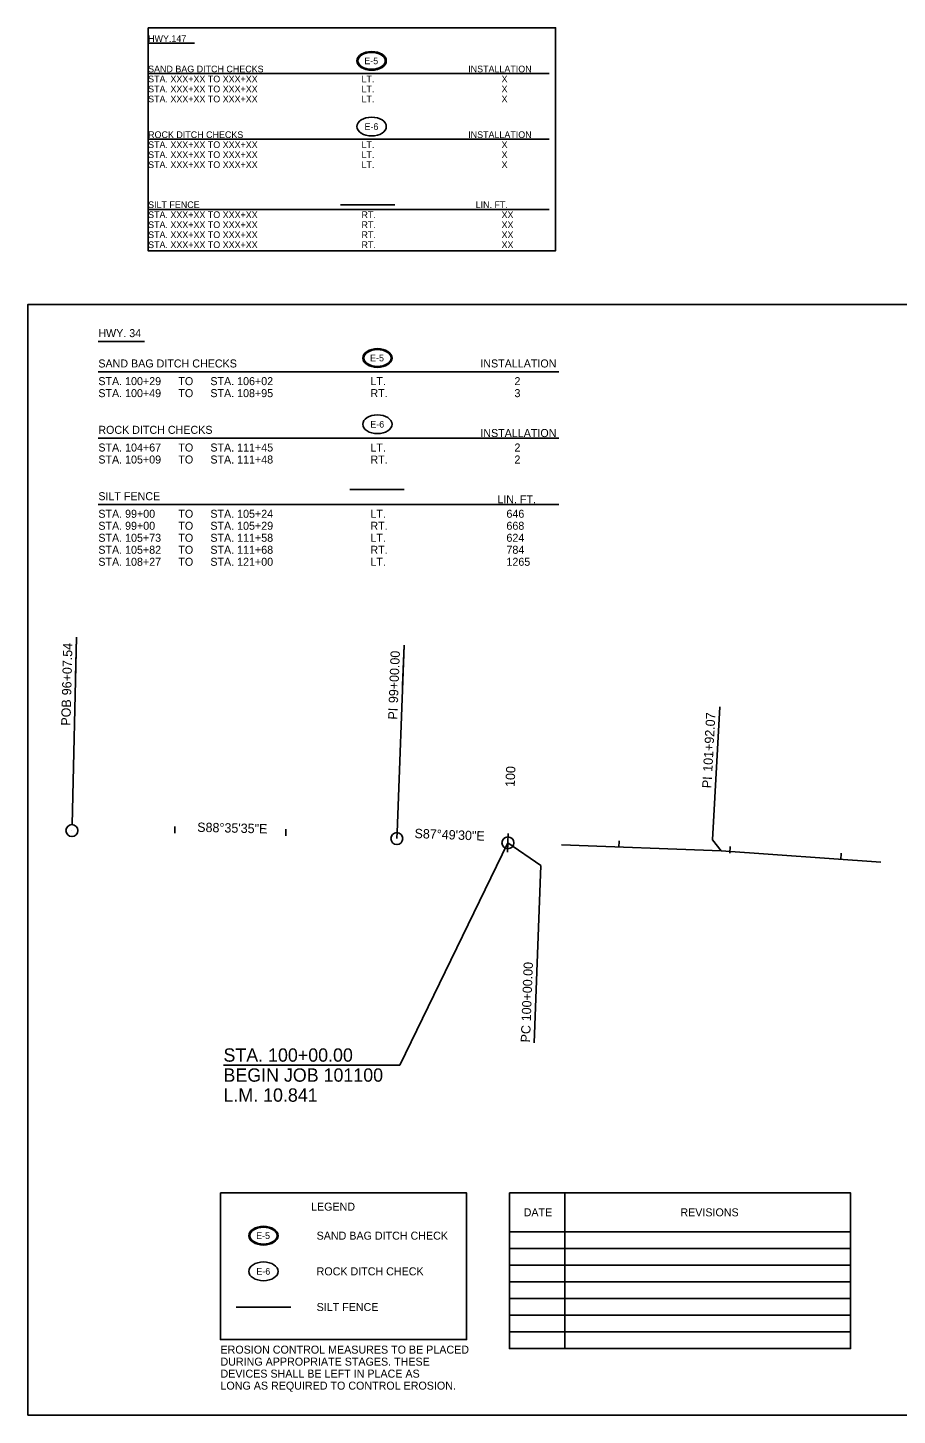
# Model space of a CAD drawing. Extents: x 1806834 to 1810084, y 678065 to 679314.
# Drawn here: x 1806834 to 1807616, y 678065 to 679314 of the extents above; entities that cross this region are included whole.
import ezdxf

# ---------------------------------------------------------------- set-up
doc = ezdxf.new("R2010")
doc.units = 0
for name, color, linetype in [('_CG DITCH CHECK', 7, 'Continuous'), ('_PROJECT LIMITS', 7, 'Continuous'), ('Default', 7, 'Continuous'), ('DSN_DRFT_Guideline-No-Plot', 7, 'Continuous'), ('DSN_RDWY_Alignment Annotation', 7, 'Continuous'), ('Erosion Legend', 7, 'Continuous'), ('R_Border Notes', 7, 'Continuous')]:
    doc.layers.add(name, color=color, linetype=linetype)

# ---------------------------------------------------------------- blocks, each defined once
blk = doc.blocks.new('E-6')
at = {"layer": 'Default'}
blk.add_ellipse((0, 0), major_axis=(1.32, 0), ratio=0.638788, dxfattribs=at)
blk.add_text('E-6', height=0.6, dxfattribs=at).set_placement((-0.64, -0.3))
blk = doc.blocks.new('E-5')
at = {"layer": 'Default'}
for major_axis, ratio in [((1.32, 0), 0.638788), ((-1.23, 0), 0.613481)]:
    blk.add_ellipse((0, 0), major_axis=major_axis, ratio=ratio, dxfattribs=at)
blk.add_text('E-5', height=0.6, dxfattribs=at).set_placement((-0.66, -0.3))

msp = doc.modelspace()

# ---------------------------------------------------------------- linework, layer by layer
at = {"layer": '_CG DITCH CHECK'}
for centre, major_axis, ratio in [((1807148.5, 679016.5), (13.2, 0), 0.638788), ((1807148.5, 679016.5), (-12.3, 0), 0.613481), ((1807046, 678227), (13.2, 0), 0.638788), ((1807046, 678227), (-12.3, 0), 0.613481)]:
    msp.add_ellipse(centre, major_axis=major_axis, ratio=ratio, dxfattribs=at)
at = {"layer": '_PROJECT LIMITS'}
for p, q in [((1807168.8, 678380.5), (1807265.9, 678580.4)), ((1807010, 678380.5), (1807168.8, 678380.5))]:
    msp.add_line(p, q, dxfattribs=at)
at = {"layer": 'Default'}
for p, q in [((1806897.3, 679031.4), (1806939, 679031.4)), ((1806897.3, 679004.1), (1807311.7, 679004.1)), ((1806897.3, 678944.4), (1807311.7, 678944.4)), ((1806897.3, 678884.7), (1807311.7, 678884.7)), ((1807317.2, 678265.5), (1807317.2, 678125.5)), ((1807267.2, 678230.5), (1807574.2, 678230.5)), ((1807267.2, 678215.5), (1807574.2, 678215.5)), ((1807267.2, 678200.5), (1807574.2, 678200.5)), ((1807267.2, 678185.5), (1807574.2, 678185.5)), ((1807267.2, 678170.5), (1807574.2, 678170.5)), ((1807267.2, 678155.5), (1807574.2, 678155.5)), ((1807267.2, 678140.5), (1807574.2, 678140.5))]:
    msp.add_line(p, q, dxfattribs=at)
for points in [[(1806942.2, 679313.6), (1807308.8, 679313.6), (1807308.8, 679113), (1806942.2, 679113)], [(1807007.3, 678265.5), (1807228.8, 678265.5), (1807228.8, 678133.5), (1807007.3, 678133.5)], [(1807267.2, 678265.5), (1807574.2, 678265.5), (1807574.2, 678125.5), (1807267.2, 678125.5)]]:
    msp.add_lwpolyline(points, close=True, dxfattribs=at)
at = {"layer": 'DSN_DRFT_Guideline-No-Plot'}
msp.add_lwpolyline([(1806833.9, 678065.5), (1808483.9, 678065.5), (1808483.9, 679064.5), (1806833.9, 679064.5)], close=True, dxfattribs=at)
at = {"layer": 'DSN_RDWY_Alignment Annotation'}
for p, q in [((1806873.8, 678596.8), (1806877.9, 678765.4)), ((1806877.9, 678765.4), (1806877, 678729.4)), ((1807166.2, 678589.6), (1807172.6, 678758.1)), ((1807172.6, 678758.1), (1807171.2, 678722.1)), ((1807450.1, 678583), (1807456.6, 678702.8)), ((1807456.6, 678702.8), (1807456.6, 678702.8)), ((1806873.6, 678591.4), (1806873.6, 678591.4)), ((1806966.2, 678595.2), (1806966.1, 678589.2)), ((1807066.2, 678592.7), (1807066, 678586.7)), ((1807166.2, 678590.2), (1807166, 678584.2)), ((1807266.2, 678588.8), (1807265.6, 678572.1)), ((1807166, 678584.2), (1807166, 678584.2)), ((1807265.9, 678580.4), (1807265.9, 678580.4)), ((1807295.4, 678559.9), (1807265.9, 678580.4)), ((1807457.9, 678573.2), (1807314, 678578.6)), ((1807366.1, 678582.2), (1807365.8, 678576.2)), ((1807450.1, 678583), (1807457.9, 678573.2)), ((1807466, 678577.1), (1807465.7, 678571.1)), ((1807457.9, 678573.2), (1807601.5, 678562.9)), ((1807565.9, 678571.1), (1807565.5, 678565.1)), ((1807295.4, 678559.9), (1807289.4, 678400.6)), ((1807289.4, 678400.6), (1807289.4, 678400.6))]:
    msp.add_line(p, q, dxfattribs=at)
for centre in [(1806873.6, 678591.4), (1807166, 678584.2), (1807265.9, 678580.4)]:
    msp.add_circle(centre, 5.34, dxfattribs=at)
at = {"layer": 'Erosion Legend'}
for p, q in [((1806942.1, 679299.7), (1806983.8, 679299.7)), ((1806942.1, 679272.4), (1807303.1, 679272.4)), ((1806942.1, 679213.3), (1807303.1, 679213.3)), ((1806942.1, 679150.1), (1807303.1, 679150.1)), ((1807115.3, 679154.3), (1807164.2, 679154.3)), ((1807123.6, 678898.1), (1807172.6, 678898.1)), ((1807021.5, 678162.8), (1807070.5, 678162.8))]:
    msp.add_line(p, q, dxfattribs=at)
at = {"layer": 'R_Border Notes'}
msp.add_line((1807267.2, 678125.5), (1807574.2, 678125.5), dxfattribs=at)

# ---------------------------------------------------------------- block references
at = {"layer": '_CG DITCH CHECK', "xscale": 10.000000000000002, "yscale": 10.000000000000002, "rotation": -1.52026910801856e-09}
msp.add_blockref('E-5', (1807143.3, 679283.8), dxfattribs=at)
at = {"layer": 'Erosion Legend', "xscale": 10, "yscale": 10, "rotation": -1.8065126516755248e-10}
for p in [(1807143.3, 679224.7), (1807148.5, 678956.9), (1807046, 678194.9)]:
    msp.add_blockref('E-6', p, dxfattribs=at)

# ---------------------------------------------------------------- texts
at = {"layer": '_CG DITCH CHECK'}
for p in [(1807141.9, 679013.5), (1807039.4, 678224)]:
    msp.add_text('E-5', height=6, dxfattribs=at).set_placement(p)
at = {"layer": '_PROJECT LIMITS'}
for s, p in [('STA. 100+00.00', (1807010, 678383.5)), ('BEGIN JOB 101100', (1807010, 678365.5)), ('L.M. 10.841', (1807010, 678347.5))]:
    msp.add_text(s, height=12, dxfattribs=at).set_placement(p)
at = {"layer": 'Default'}
for s, p in [('HWY. 34', (1806897.4, 679035.3)), ('SAND BAG DITCH CHECKS', (1806897.4, 679008)), ('INSTALLATION', (1807241.1, 679008)), ('STA. 100+29 ', (1806897.4, 678992.1)), ('STA. 100+49', (1806897.4, 678981.3)), ('TO ', (1806969.4, 678992.1)), ('TO ', (1806969.4, 678981.3)), ('STA. 106+02', (1806998.2, 678992.1)), ('STA. 108+95', (1806998.2, 678981.3)), ('LT.', (1807142.2, 678992.1)), ('RT.', (1807142.2, 678981.3)), ('3', (1807271.8, 678981.3)), ('2', (1807271.8, 678992.1)), ('ROCK DITCH CHECKS', (1806897.4, 678948.3)), ('INSTALLATION', (1807241.1, 678945.4)), ('STA. 104+67 ', (1806897.4, 678932.4)), ('TO ', (1806969.4, 678932.4)), ('STA. 111+45', (1806998.2, 678932.4)), ('LT.', (1807142.2, 678932.4)), ('2', (1807271.8, 678932.4)), ('STA. 105+09', (1806897.4, 678921.6)), ('TO ', (1806969.4, 678921.6)), ('STA. 111+48', (1806998.2, 678921.6)), ('RT.', (1807142.2, 678921.6)), ('2', (1807271.8, 678921.6)), ('SILT FENCE', (1806897.4, 678888.6)), ('LIN. FT.', (1807256.4, 678885.8)), ('STA. 99+00 ', (1806897.4, 678872.8)), ('TO ', (1806969.4, 678872.8)), ('STA. 105+24', (1806998.2, 678872.8)), ('LT.', (1807142.2, 678872.8)), ('646', (1807264.6, 678872.8)), ('STA. 99+00 ', (1806897.4, 678862)), ('TO ', (1806969.4, 678862)), ('STA. 105+29', (1806998.2, 678862)), ('RT.', (1807142.2, 678862)), ('668', (1807264.6, 678862)), ('STA. 105+73', (1806897.4, 678851.2)), ('TO', (1806969.4, 678851.2)), ('STA. 111+58', (1806998.2, 678851.2)), ('LT.', (1807142.2, 678851.2)), ('624', (1807264.6, 678851.2)), ('STA. 105+82', (1806897.4, 678840.4)), ('TO', (1806969.4, 678840.4)), ('STA. 111+68', (1806998.2, 678840.4)), ('RT.', (1807142.2, 678840.4)), ('784', (1807264.6, 678840.4)), ('STA. 108+27', (1806897.4, 678829.6)), ('TO', (1806969.4, 678829.6)), ('STA. 121+00', (1806998.2, 678829.6)), ('LT.', (1807142.2, 678829.6)), ('1265', (1807264.6, 678829.6)), ('LEGEND', (1807088.8, 678249.5)), ('DATE', (1807280.1, 678244.4)), ('REVISIONS', (1807421.1, 678244.4)), ('SAND BAG DITCH CHECK', (1807093.8, 678223.4)), ('ROCK DITCH CHECK', (1807093.8, 678191.3)), ('SILT FENCE', (1807093.8, 678159.2)), ('EROSION CONTROL MEASURES TO BE PLACED', (1807007.3, 678120.9)), ('DURING APPROPRIATE STAGES. THESE ', (1807007.3, 678110.1)), ('DEVICES SHALL BE LEFT IN PLACE AS ', (1807007.3, 678099.3)), ('LONG AS REQUIRED TO CONTROL EROSION.', (1807007.3, 678088.5))]:
    msp.add_text(s, height=7.2, dxfattribs=at).set_placement(p)
at = {"layer": 'DSN_RDWY_Alignment Annotation'}
for s, rotation, p in [('96+07.54', 88.593, (1806873, 678713)), ('99+00.00', 87.8251, (1807167, 678705.9)), ('POB ', 88.593, (1806872.3, 678685.7)), ('PI ', 87.8251, (1807166.5, 678691.1)), ('101+92.07', 86.8648, (1807449.8, 678644.1)), ('100', 87.8251, (1807272, 678630.5)), ('PI ', 86.8648, (1807449, 678629.3)), ('S88°35\'35"E', 358.593, (1806986.3, 678590.3)), ('S87°49\'30"E', 357.8251, (1807181.8, 678584.7)), ('100+00.00', 87.8251, (1807286.5, 678419.7)), ('PC', 87.8251, (1807285.8, 678400.7))]:
    msp.add_text(s, height=8.4, rotation=rotation, dxfattribs=at).set_placement(p)
at = {"layer": 'Erosion Legend'}
for s, p in [('HWY.147', (1806942.2, 679300.8)), ('SAND BAG DITCH CHECKS', (1806942.2, 679273.5)), ('INSTALLATION', (1807230.2, 679273.5)), ('STA. XXX+XX TO XXX+XX', (1806942.2, 679264.5)), ('LT.', (1807134.2, 679264.5)), ('X', (1807260.2, 679264.5)), ('STA. XXX+XX TO XXX+XX', (1806942.2, 679255.5)), ('STA. XXX+XX TO XXX+XX', (1806942.2, 679246.5)), ('LT.  ', (1807134.2, 679255.5)), ('LT.  ', (1807134.2, 679246.5)), ('X', (1807260.2, 679255.5)), ('X', (1807260.2, 679246.5)), ('ROCK DITCH CHECKS', (1806942.2, 679214.4)), ('INSTALLATION', (1807230.2, 679214.4)), ('STA. XXX+XX TO XXX+XX', (1806942.2, 679205.4)), ('STA. XXX+XX TO XXX+XX', (1806942.2, 679196.4)), ('LT.', (1807134.2, 679205.4)), ('LT.  ', (1807134.2, 679196.4)), ('X', (1807260.2, 679205.4)), ('X', (1807260.2, 679196.4)), ('STA. XXX+XX TO XXX+XX', (1806942.2, 679187.4)), ('LT.  ', (1807134.2, 679187.4)), ('X', (1807260.2, 679187.4)), ('SILT FENCE', (1806942.2, 679151.4)), ('   LIN. FT.', (1807230.2, 679151.4)), ('STA. XXX+XX TO XXX+XX', (1806942.2, 679142.4)), ('STA. XXX+XX TO XXX+XX', (1806942.2, 679133.4)), ('RT.', (1807134.2, 679142.4)), ('RT. ', (1807134.2, 679133.4)), ('XX', (1807260.2, 679142.4)), ('XX ', (1807260.2, 679133.4)), ('STA. XXX+XX TO XXX+XX', (1806942.2, 679124.4)), ('RT. ', (1807134.2, 679124.4)), ('XX  ', (1807260.2, 679124.4)), ('STA. XXX+XX TO XXX+XX', (1806942.2, 679115.4)), ('RT. ', (1807134.2, 679115.4)), ('XX  ', (1807260.2, 679115.4))]:
    msp.add_text(s, height=6, dxfattribs=at).set_placement(p)

doc.saveas('drawing.dxf')
